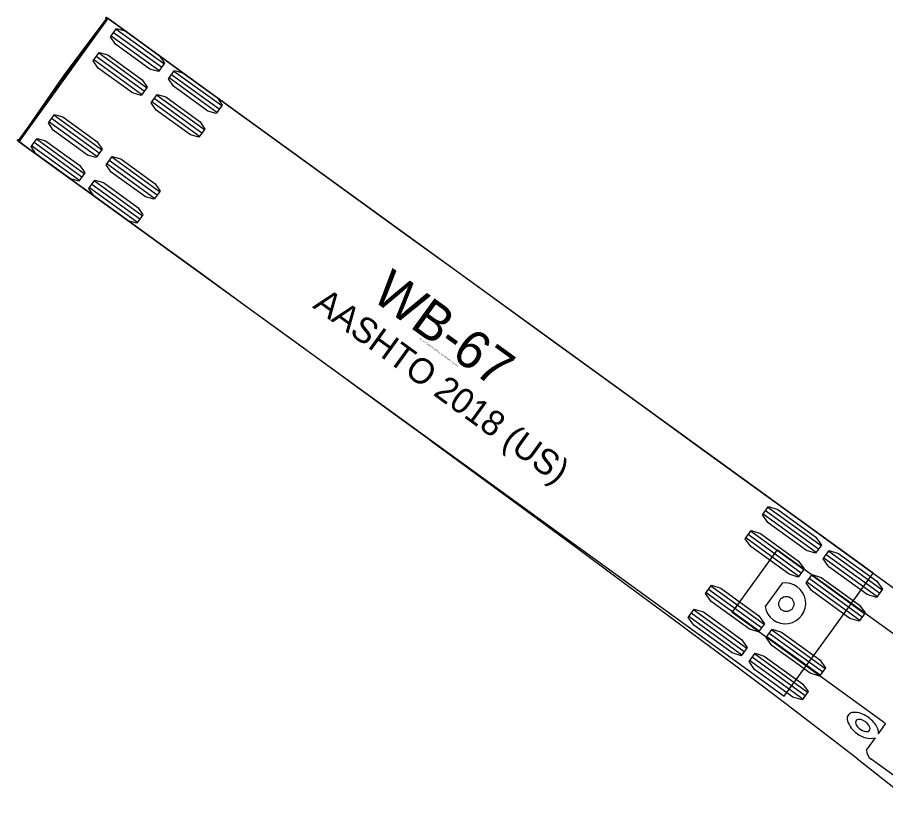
# Model space of a CAD drawing. Extents: x 973688 to 979179, y 703586 to 707602.
# Drawn here: x 977743.88 to 977792.46, y 704470.42 to 704514.96 of the extents above; entities that cross this region are included whole.
import ezdxf

# ---------------------------------------------------------------- set-up
doc = ezdxf.new("R2010")
doc.units = 0
doc.layers.add('SB Left', color=7, linetype='Continuous')

msp = doc.modelspace()

# ---------------------------------------------------------------- linework, layer by layer
at = {"layer": 'SB Left'}
for p, q in [((977743.976, 704508.003), (977748.963, 704514.886)), ((977748.878, 704514.889), (977746.745, 704511.945)), ((977748.879, 704514.89), (977748.878, 704514.889)), ((977748.905, 704514.927), (977748.893, 704514.91)), ((977748.963, 704514.886), (977748.905, 704514.927)), ((977753.552, 704511.561), (977748.963, 704514.886)), ((977751.806, 704511.978), (977749.134, 704513.914)), ((977751.94, 704512.163), (977749.268, 704514.099)), ((977752.075, 704512.349), (977749.403, 704514.285)), ((977751.107, 704511.013), (977748.434, 704512.949)), ((977750.838, 704510.641), (977748.166, 704512.578)), ((977750.972, 704510.827), (977748.3, 704512.763)), ((977746.666, 704511.957), (977746.509, 704511.741)), ((977746.568, 704511.701), (977746.724, 704511.916)), ((977746.667, 704511.958), (977746.666, 704511.957)), ((977746.724, 704511.917), (977746.667, 704511.958)), ((977746.745, 704511.945), (977746.724, 704511.917)), ((977755.314, 704510.002), (977752.642, 704511.938)), ((977746.564, 704511.696), (977746.258, 704511.274)), ((977746.412, 704511.486), (977746.469, 704511.445)), ((977755.045, 704509.631), (977752.373, 704511.567)), ((977755.18, 704509.816), (977752.507, 704511.752)), ((977791.767, 704483.872), (977753.552, 704511.561)), ((977746.08, 704511.027), (977743.947, 704508.083)), ((977746.201, 704511.315), (977746.044, 704511.099)), ((977746.044, 704511.099), (977746.044, 704511.097)), ((977746.044, 704511.097), (977746.1, 704511.056)), ((977746.1, 704511.056), (977746.08, 704511.027)), ((977746.101, 704511.056), (977746.256, 704511.271)), ((977754.346, 704508.666), (977751.674, 704510.602)), ((977754.077, 704508.294), (977751.405, 704510.231)), ((977754.211, 704508.48), (977751.539, 704510.416)), ((977748.594, 704507.544), (977745.921, 704509.48)), ((977748.325, 704507.173), (977745.652, 704509.109)), ((977748.459, 704507.358), (977745.787, 704509.295)), ((977743.932, 704508.063), (977743.919, 704508.045)), ((977743.919, 704508.045), (977743.976, 704508.004)), ((977743.947, 704508.083), (977743.946, 704508.082)), ((977747.625, 704506.208), (977744.953, 704508.144)), ((977743.976, 704508.004), (977748.565, 704504.678)), ((977747.357, 704505.837), (977744.684, 704507.773)), ((977747.491, 704506.022), (977744.819, 704507.959)), ((977751.833, 704505.197), (977749.16, 704507.133)), ((977751.564, 704504.826), (977748.891, 704506.762)), ((977751.698, 704505.011), (977749.026, 704506.948)), ((977750.73, 704503.675), (977748.058, 704505.612)), ((977750.865, 704503.861), (977748.192, 704505.797)), ((977750.596, 704503.49), (977747.923, 704505.426)), ((977748.565, 704504.678), (977786.78, 704476.989)), ((977788.572, 704485.03), (977785.602, 704487.181)), ((977788.706, 704485.215), (977785.737, 704487.367)), ((977788.841, 704485.401), (977785.871, 704487.552)), ((977787.872, 704484.065), (977784.903, 704486.216)), ((977787.603, 704483.694), (977784.634, 704485.845)), ((977787.738, 704483.879), (977784.769, 704486.03)), ((977785.143, 704483.423), (977786.414, 704485.176)), ((977786.414, 704485.176), (977794.805, 704479.097)), ((977791.973, 704482.565), (977789.003, 704484.717)), ((977792.107, 704482.751), (977789.138, 704484.902)), ((977792.242, 704482.937), (977789.272, 704485.088)), ((977791.273, 704481.6), (977788.304, 704483.752)), ((977789.273, 704480.431), (977791.767, 704483.872)), ((977783.873, 704481.67), (977785.143, 704483.423)), ((977786.661, 704483.315), (977785.712, 704482.006)), ((977791.005, 704481.229), (977788.035, 704483.381)), ((977791.139, 704481.415), (977788.17, 704483.566)), ((977785.384, 704480.63), (977782.414, 704482.781)), ((977785.518, 704480.815), (977782.549, 704482.967)), ((977785.653, 704481.001), (977782.683, 704483.152)), ((977784.684, 704479.665), (977781.715, 704481.816)), ((977784.416, 704479.294), (977781.446, 704481.445)), ((977784.55, 704479.479), (977781.581, 704481.631)), ((977792.264, 704475.59), (977783.873, 704481.67)), ((977788.919, 704478.351), (977785.95, 704480.503)), ((977789.054, 704478.537), (977786.084, 704480.688)), ((977786.78, 704476.989), (977789.273, 704480.431)), ((977788.785, 704478.166), (977785.816, 704480.317)), ((977787.817, 704476.829), (977784.847, 704478.981)), ((977787.951, 704477.015), (977784.982, 704479.166)), ((977788.086, 704477.201), (977785.116, 704479.352)), ((977792.456, 704475.45), (977792.264, 704475.59)), ((977792.054, 704474.894), (977792.456, 704475.45)), ((977791.393, 704473.982), (977791.889, 704474.666)), ((977795.84, 704470.424), (977791.648, 704473.461))]:
    msp.add_line(p, q, dxfattribs=at)
for points in [[(977793.275, 704471.59), (977790.985, 704473.394), (977790.73, 704473.593), (977788.16, 704475.577), (977786.867, 704476.563), (977785.569, 704477.546), (977782.964, 704479.503), (977782.179, 704480.088), (977780.347, 704481.452), (977777.721, 704483.397), (977775.081, 704485.345), (977772.43, 704487.297), (977769.776, 704489.245), (977767.126, 704491.184), (977766.862, 704491.378), (977764.491, 704493.109), (977761.869, 704495.021), (977759.251, 704496.926), (977756.635, 704498.826), (977754.109, 704500.66), (977751.843, 704502.302), (977749.577, 704503.945), (977747.75, 704505.269), (977746.914, 704505.875), (977746.079, 704506.479), (977745.245, 704507.083), (977744.413, 704507.686), (977744.005, 704507.996), (977744.212, 704508.399), (977746.463, 704511.662), (977748.902, 704514.93)], [(977748.902, 704514.93), (977750.304, 704513.915), (977751.741, 704512.874), (977753.188, 704511.826), (977754.646, 704510.77), (977756.114, 704509.706), (977757.719, 704508.543), (977759.348, 704507.362), (977760.965, 704506.19), (977762.954, 704504.749), (977765.669, 704502.782), (977768.389, 704500.811), (977771.116, 704498.835), (977773.86, 704496.847), (977776.621, 704494.846), (977779.39, 704492.84), (977782.159, 704490.834), (977784.92, 704488.833), (977787.673, 704486.839), (977790.424, 704484.845), (977793.176, 704482.85)]]:
    msp.add_lwpolyline(points, dxfattribs=at)
for points in [[(977752.108, 704512.395), (977751.773, 704511.932), (977751.297, 704512.063), (977749.373, 704513.457), (977749.1, 704513.868), (977749.436, 704514.331), (977749.911, 704514.199), (977751.835, 704512.805)], [(977751.14, 704511.059), (977750.804, 704510.595), (977750.329, 704510.727), (977748.405, 704512.121), (977748.132, 704512.532), (977748.468, 704512.995), (977748.943, 704512.863), (977750.867, 704511.469)], [(977755.347, 704510.048), (977755.012, 704509.585), (977754.536, 704509.716), (977752.612, 704511.11), (977752.339, 704511.521), (977752.675, 704511.984), (977753.15, 704511.852), (977755.074, 704510.458)], [(977754.379, 704508.712), (977754.044, 704508.248), (977753.568, 704508.38), (977751.644, 704509.774), (977751.371, 704510.185), (977751.707, 704510.648), (977752.182, 704510.516), (977754.106, 704509.122)], [(977748.627, 704507.59), (977748.291, 704507.127), (977747.816, 704507.258), (977745.892, 704508.652), (977745.619, 704509.063), (977745.955, 704509.526), (977746.43, 704509.395), (977748.354, 704508.001)], [(977747.659, 704506.254), (977747.323, 704505.791), (977746.848, 704505.922), (977744.924, 704507.316), (977744.651, 704507.727), (977744.987, 704508.19), (977745.462, 704508.059), (977747.386, 704506.665)], [(977751.866, 704505.243), (977751.53, 704504.78), (977751.055, 704504.911), (977749.131, 704506.306), (977748.858, 704506.716), (977749.194, 704507.179), (977749.669, 704507.048), (977751.593, 704505.654)], [(977750.898, 704503.907), (977750.562, 704503.444), (977750.087, 704503.575), (977748.163, 704504.969), (977747.89, 704505.38), (977748.226, 704505.843), (977748.701, 704505.712), (977750.625, 704504.318)], [(977788.874, 704485.447), (977788.538, 704484.984), (977788.021, 704485.145), (977785.884, 704486.694), (977785.569, 704487.135), (977785.905, 704487.598), (977786.422, 704487.437), (977788.559, 704485.888)], [(977787.906, 704484.111), (977787.57, 704483.647), (977787.053, 704483.809), (977784.916, 704485.358), (977784.601, 704485.799), (977784.937, 704486.262), (977785.453, 704486.1), (977787.591, 704484.551)], [(977792.275, 704482.983), (977791.939, 704482.519), (977791.423, 704482.681), (977789.285, 704484.23), (977788.97, 704484.671), (977789.306, 704485.134), (977789.823, 704484.972), (977791.96, 704483.423)], [(977791.307, 704481.646), (977790.971, 704481.183), (977790.454, 704481.345), (977788.317, 704482.894), (977788.002, 704483.335), (977788.338, 704483.798), (977788.854, 704483.636), (977790.992, 704482.087)], [(977785.686, 704481.047), (977785.35, 704480.584), (977784.834, 704480.745), (977782.696, 704482.294), (977782.381, 704482.735), (977782.717, 704483.198), (977783.234, 704483.037), (977785.371, 704481.488)], [(977784.718, 704479.711), (977784.382, 704479.248), (977783.865, 704479.409), (977781.728, 704480.958), (977781.413, 704481.399), (977781.749, 704481.862), (977782.265, 704481.701), (977784.403, 704480.152)], [(977789.087, 704478.583), (977788.751, 704478.12), (977788.235, 704478.281), (977786.097, 704479.83), (977785.782, 704480.271), (977786.118, 704480.734), (977786.635, 704480.572), (977788.772, 704479.023)], [(977788.119, 704477.247), (977787.783, 704476.783), (977787.266, 704476.945), (977785.129, 704478.494), (977784.814, 704478.935), (977785.15, 704479.398), (977785.667, 704479.236), (977787.804, 704477.687)]]:
    msp.add_lwpolyline(points, close=True, dxfattribs=at)
for centre, radius in [((977748.858, 704514.92), 0.0266), ((977743.911, 704508.093), 0.0266), ((977786.901, 704482.149), 0.424)]:
    msp.add_circle(centre, radius, dxfattribs=at)
for centre, radius, start, end in [((977748.858, 704514.92), 0.0363, 343.1516, 304.313), ((977746.538, 704511.72), 0.0352, 144.0994, 323.0998), ((977746.538, 704511.72), 0.0353, 327.4103, 145.76), ((977746.229, 704511.294), 0.0354, 148.3657, 320.5512), ((977746.229, 704511.294), 0.0352, 325.0485, 144.0489), ((977742.295, 704509.249), 2.022, 324.0742, 324.7579), ((977786.841, 704482.187), 1.143, 189.0742, 99.0742), ((977790.644, 704475.736), 0.346, 103.6684, 200.6815), ((977790.726, 704474.948), 1.136, 56.7895, 98.3102), ((977791.659, 704476.077), 1.416, 199.0782, 236.146), ((977790.943, 704475.524), 0.172, 116.622, 203.7726), ((977790.989, 704475.337), 0.362, 60.7366, 109.7776), ((977790.902, 704474.97), 0.732, 22.6659, 68.9003), ((977790.49, 704474.396), 1.73, 35.449, 60.2475), ((977791.407, 704475.692), 0.664, 200.9486, 239.1703), ((977791.388, 704475.533), 0.522, 231.9047, 279.0688), ((977791.425, 704475.179), 0.169, 285.5211, 25.6398), ((977791.327, 704474.948), 0.729, 355.7517, 38.2657), ((977791.605, 704475.766), 1.136, 229.6529, 284.4442), ((977792.012, 704473.963), 0.619, 178.2345, 234.0762)]:
    msp.add_arc(centre, radius, start, end, dxfattribs=at)

# ---------------------------------------------------------------- texts
for s, height, p in [('WB-67', 2.125, (977763.612, 704499.234)), ('AASHTO 2018 (US)', 1.41667, (977760.356, 704498.75)), ('(c) 2022 Transoft Solutions, Inc. All rights reserved.', 0.085, (977766.38, 704496.966))]:
    msp.add_text(s, height=height, rotation=324.0742, dxfattribs=at).set_placement(p)

doc.saveas('drawing.dxf')
